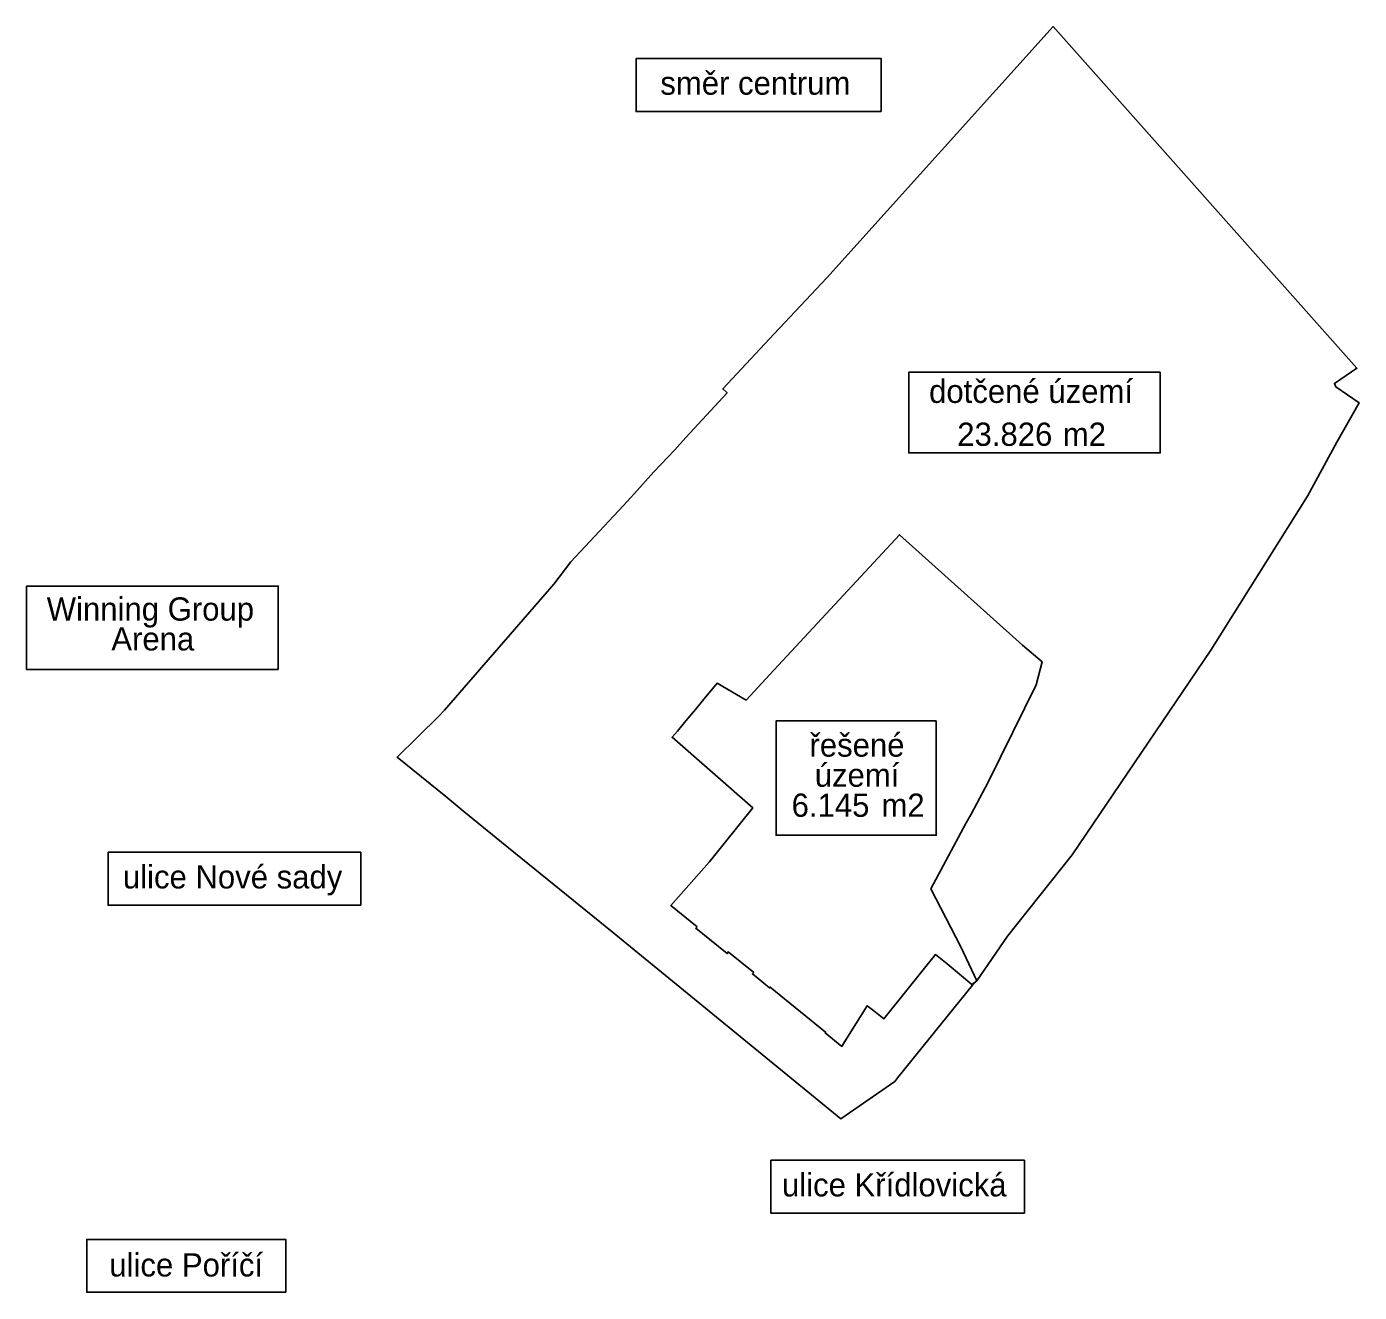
# Model space of a CAD drawing. Extents: x -598686 to -598363, y -1161930 to -1161624.
import ezdxf

# ---------------------------------------------------------------- set-up
doc = ezdxf.new("R2010")
doc.units = 0
for name, color, linetype in [('kam_bublina', 7, 'Continuous'), ('kam_popis_uzemi', 7, 'Continuous'), ('kam_resene_uzemi', 7, 'Continuous'), ('popis_ramecek_doplnek', 7, 'Continuous'), ('resene_uzemi_doplnek', 7, 'Continuous'), ('resene_uzemi_doplnek_popis', 7, 'Continuous')]:
    doc.layers.add(name, color=color, linetype=linetype)

msp = doc.modelspace()

# ---------------------------------------------------------------- linework, layer by layer
at = {"layer": 'kam_bublina'}
for points in [[(-598411.47, -1161707.66), (-598472.34, -1161707.66), (-598472.34, -1161727.18), (-598411.47, -1161727.18)], [(-598465.68, -1161792.06), (-598504.45, -1161792.06), (-598504.45, -1161819.73), (-598465.68, -1161819.73)]]:
    msp.add_lwpolyline(points, close=True, dxfattribs=at)
at = {"layer": 'kam_resene_uzemi'}
msp.add_lwpolyline([(-598520.61, -1161826.23), (-598529.88, -1161836.77), (-598523.53, -1161841.92), (-598523.86, -1161842.23), (-598516.25, -1161848.35), (-598516.04, -1161847.98), (-598509.85, -1161852.98), (-598510.15, -1161853.31), (-598505.99, -1161856.7), (-598505.86, -1161856.47), (-598492.44, -1161867.39), (-598492.54, -1161867.57), (-598488.54, -1161870.83), (-598487.13, -1161868.63), (-598482.36, -1161860.99), (-598480.8, -1161862.25), (-598478.34, -1161864.14), (-598468.86, -1161852.32), (-598465.88, -1161848.61), (-598462.99, -1161850.87), (-598457.05, -1161855.89), (-598455.84, -1161854.98), (-598459.74, -1161846.72), (-598467, -1161832.7), (-598458.45, -1161816.73), (-598457.26, -1161814.63), (-598453.12, -1161806.91), (-598447.12, -1161794.75), (-598441.46, -1161783.3), (-598440.02, -1161777.77), (-598444.82, -1161773.72), (-598474.53, -1161747.01), (-598505.91, -1161780.84), (-598511.67, -1161787.03), (-598518.7, -1161782.94), (-598522.22, -1161787.19), (-598523.94, -1161789.27), (-598526.24, -1161792.04), (-598528.28, -1161794.51), (-598529.59, -1161796), (-598510.08, -1161813.08)], close=True, dxfattribs=at)
at = {"layer": 'popis_ramecek_doplnek'}
for points in [[(-598478.97, -1161644.56), (-598538.29, -1161644.56), (-598538.29, -1161631.74), (-598478.97, -1161631.74)], [(-598624.91, -1161779.65), (-598685.79, -1161779.65), (-598685.79, -1161759.41), (-598624.91, -1161759.41)], [(-598604.94, -1161836.68), (-598666.06, -1161836.68), (-598666.06, -1161823.86), (-598604.94, -1161823.86)], [(-598444.32, -1161911.22), (-598505.69, -1161911.22), (-598505.69, -1161898.4), (-598444.32, -1161898.4)], [(-598623.08, -1161930.36), (-598671.23, -1161930.36), (-598671.23, -1161917.54), (-598623.08, -1161917.54)]]:
    msp.add_lwpolyline(points, close=True, dxfattribs=at)
at = {"layer": 'resene_uzemi_doplnek'}
msp.add_lwpolyline([(-598448.42, -1161844.15), (-598432.81, -1161824.48), (-598399.24, -1161774.92), (-598375.81, -1161737.68), (-598368.73, -1161724.58), (-598363.29, -1161715.1), (-598368.95, -1161711.17), (-598369.31, -1161710.36), (-598363.88, -1161706.68), (-598437.38, -1161624.02), (-598492.18, -1161684.79), (-598504.87, -1161698.37), (-598517.33, -1161711.7), (-598516.27, -1161712.67), (-598526.27, -1161723.47), (-598528.95, -1161726.46), (-598534, -1161731.8), (-598538.76, -1161737.11), (-598541.41, -1161740.03), (-598554.08, -1161753.52), (-598558.22, -1161758.94), (-598584.7, -1161789.42), (-598586.01, -1161790.91), (-598596.16, -1161800.8), (-598584.37, -1161810.37), (-598579.98, -1161813.99), (-598570.86, -1161821.38), (-598544.13, -1161843.14), (-598488.77, -1161888.33), (-598475.71, -1161879.32), (-598474.94, -1161878.34), (-598456.9, -1161856.04), (-598455.84, -1161854.99), (-598455.84, -1161854.98), (-598457.05, -1161855.89), (-598462.99, -1161850.87), (-598465.88, -1161848.61), (-598468.86, -1161852.32), (-598478.34, -1161864.14), (-598480.8, -1161862.25), (-598482.36, -1161860.99), (-598487.13, -1161868.63), (-598487.84, -1161869.76), (-598488.54, -1161870.83), (-598492.54, -1161867.57), (-598492.44, -1161867.39), (-598505.86, -1161856.47), (-598505.99, -1161856.7), (-598510.15, -1161853.31), (-598509.85, -1161852.98), (-598516.04, -1161847.98), (-598516.25, -1161848.35), (-598523.86, -1161842.23), (-598523.53, -1161841.92), (-598529.88, -1161836.77), (-598520.61, -1161826.23), (-598510.08, -1161813.08), (-598529.59, -1161796), (-598528.28, -1161794.51), (-598526.24, -1161792.04), (-598523.94, -1161789.27), (-598522.22, -1161787.19), (-598518.7, -1161782.94), (-598511.67, -1161787.03), (-598505.91, -1161780.84), (-598474.53, -1161747.01), (-598444.82, -1161773.72), (-598440.02, -1161777.77), (-598441.46, -1161783.3), (-598447.12, -1161794.75), (-598453.12, -1161806.91), (-598457.26, -1161814.63), (-598458.45, -1161816.73), (-598467, -1161832.7), (-598459.74, -1161846.72), (-598455.84, -1161854.98), (-598455.84, -1161854.99)], close=True, dxfattribs=at)

# ---------------------------------------------------------------- texts
at = {"layer": 'kam_popis_uzemi'}
for s, p in [('směr centrum', (-598532.44, -1161640.49)), ('Winning Group ', (-598680.93, -1161767.78)), ('Arena', (-598665.3, -1161775.01)), ('ulice Nové sady', (-598662.5, -1161832.61)), ('ulice Křídlovická', (-598503, -1161907.15)), ('ulice Poříčí', (-598665.78, -1161926.53))]:
    msp.add_text(s, height=5.625, dxfattribs=at).set_placement(p)
at = {"layer": 'kam_resene_uzemi'}
for s, p in [('řešené ', (-598496.35, -1161800.71)), ('území', (-598495.09, -1161807.99)), ('6.145', (-598500.67, -1161815.27)), (' m2', (-598481.02, -1161815.27))]:
    msp.add_text(s, height=5.625, dxfattribs=at).set_placement(p)
at = {"layer": 'resene_uzemi_doplnek_popis'}
for s, p in [('dotčené území', (-598467.4, -1161715.09)), ('23.826', (-598460.59, -1161725.48)), (' m2', (-598437.14, -1161725.48))]:
    msp.add_text(s, height=5.625, dxfattribs=at).set_placement(p)

doc.saveas('drawing.dxf')
